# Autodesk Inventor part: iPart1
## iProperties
Shininess: 64.0
Length Units: 11269
Angle Units: 11279
Time Units: 11290
Mass Units: 11283
Length Display Precision: 3
Angle Display Precision: 2
Compacted: True
Part Number: iPart1
Document SubType Name: Modeling
Created: 2003-01
Designer: Owner
Density: 0.0
Volumn: 0.0
Area: 0.0
PropertySet Name: Model Information
Control State: 0
Master: False
Checked Out: False
Author: Owner
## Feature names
1. Extrusion1
2. Fillet1
